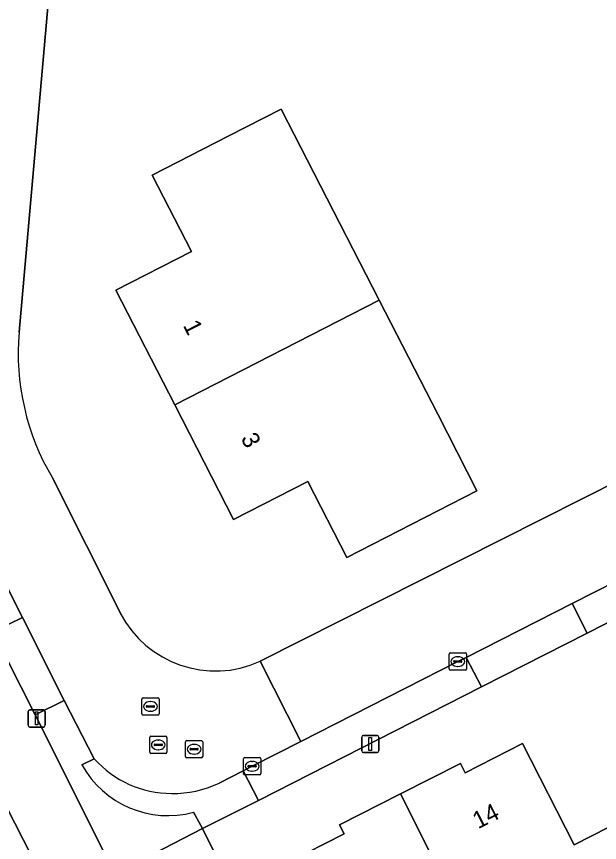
# Model space of a CAD drawing. Extents: x 162722 to 165104, y 384719 to 386284.
# Drawn here: x 163950.78 to 163984.67, y 385101.85 to 385149.88 of the extents above; entities that cross this region are included whole.
import ezdxf

# ---------------------------------------------------------------- set-up
doc = ezdxf.new("R2010")
doc.units = 0
for name, color, linetype in [('IMGEO_Erf', 7, 'Continuous'), ('IMGEO_Kolk', 7, 'Continuous'), ('IMGEO_Lichtmast', 7, 'Continuous'), ('IMGEO_Pand', 7, 'Continuous'), ('IMGEO_Pand_nummerreeks', 7, 'Continuous'), ('IMGEO_Parkeervlak_open', 7, 'Continuous'), ('IMGEO_Rijbaan_lokaal_gesloten', 7, 'Continuous'), ('IMGEO_Rioolput', 7, 'Continuous'), ('IMGEO_Voetpad_open', 7, 'Continuous')]:
    doc.layers.add(name, color=color, linetype=linetype)

msp = doc.modelspace()

# ---------------------------------------------------------------- linework, layer by layer
at = {"layer": 'IMGEO_Erf'}
for points in [[(163954.865, 385176.188), (163950.926, 385131.52)], [(163925.634, 385124.386), (163926.79, 385136.924), (163927.93, 385149.301), (163931.403, 385148.981), (163936.381, 385148.522), (163935.933, 385143.661), (163940.873, 385143.206), (163940.181, 385135.69), (163939.488, 385128.173), (163934.624, 385128.621), (163934.161, 385123.598), (163935.481, 385121.023), (163935.921, 385121.248), (163938.196, 385116.808), (163942.568, 385119.048), (163946.07, 385112.214), (163941.667, 385109.956), (163943.925, 385105.548), (163948.225, 385107.751), (163951.644, 385101.078)], [(163964.943, 385112.381), (164000, 385130.066), (164025.009, 385142.682)], [(163952.865, 385123.051), (163956.817, 385115.183)], [(163956.503, 385100.031), (163951.859, 385109.26), (163949.405, 385114.092), (163945.936, 385121.003)], [(163997.359, 385120.835), (163983.951, 385114.019), (163977.81, 385110.894), (163964.844, 385104.297), (163961.595, 385102.65), (163964.334, 385097.182), (163965.557, 385094.815), (163966.315, 385093.275), (163969.491, 385094.891), (163968.713, 385096.419), (163966.546, 385100.679), (163969.83, 385102.351), (163969.568, 385102.866), (163973.106, 385104.666), (163976.594, 385106.441), (163976.87, 385105.899), (163980.209, 385107.598), (163983.201, 385101.719), (163986.206, 385103.248)]]:
    msp.add_lwpolyline(points, dxfattribs=at)
msp.add_lwpolyline([(163975.271, 385126.75), (163977.551, 385122.3), (163969.982, 385118.421), (163967.715, 385122.845), (163963.394, 385120.631), (163959.98, 385127.292), (163956.564, 385133.957), (163960.956, 385136.208), (163958.676, 385140.656), (163963.126, 385142.937), (163966.174, 385144.499), (163971.87, 385133.386)], close=True, dxfattribs=at)
for centre, radius, start, end in [((163965.158, 385130.322), 14.282, 175.1881, 210.6034), ((163962.351, 385118.049), 6.233, 207.3794, 294.5703)]:
    msp.add_arc(centre, radius, start, end, dxfattribs=at)
at = {"layer": 'IMGEO_Kolk'}
for p, q in [((163975.937, 385111.943), (163975.937, 385112.795)), ((163976.012, 385112.869), (163976.864, 385112.869)), ((163976.425, 385112.649), (163976.45, 385112.649)), ((163976.938, 385112.795), (163976.938, 385111.943)), ((163976.196, 385112.363), (163976.196, 385112.375)), ((163976.634, 385112.326), (163976.236, 385112.326)), ((163976.239, 385112.412), (163976.637, 385112.412)), ((163976.68, 385112.375), (163976.68, 385112.363)), ((163976.864, 385111.869), (163976.012, 385111.869)), ((163976.448, 385112.089), (163976.423, 385112.089)), ((163963.979, 385105.853), (163963.979, 385106.705)), ((163964.054, 385106.779), (163964.906, 385106.779)), ((163964.467, 385106.559), (163964.492, 385106.559)), ((163964.98, 385106.705), (163964.98, 385105.853)), ((163964.238, 385106.273), (163964.238, 385106.285)), ((163964.676, 385106.236), (163964.278, 385106.236)), ((163964.281, 385106.322), (163964.679, 385106.322)), ((163964.49, 385105.999), (163964.465, 385105.999)), ((163964.722, 385106.285), (163964.722, 385106.273)), ((163964.906, 385105.779), (163964.054, 385105.779))]:
    msp.add_line(p, q, dxfattribs=at)
for points in [[(163975.937, 385111.943), (163975.937, 385112.795)], [(163976.012, 385112.869), (163976.864, 385112.869)], [(163976.938, 385112.795), (163976.938, 385111.943)], [(163976.864, 385111.869), (163976.012, 385111.869)], [(163963.979, 385105.853), (163963.979, 385106.705)], [(163964.054, 385106.779), (163964.906, 385106.779)], [(163964.98, 385106.705), (163964.98, 385105.853)], [(163964.906, 385105.779), (163964.054, 385105.779)]]:
    msp.add_lwpolyline(points, dxfattribs=at)
for centre, radius, start, end in [((163976.014, 385112.793), 0.0765, 91.552, 178.448), ((163976.014, 385112.793), 0.0765, 91.552, 178.448), ((163976.862, 385112.793), 0.0765, 1.552, 88.448), ((163976.862, 385112.793), 0.0765, 1.552, 88.448), ((163976.236, 385112.372), 0.0403, 85.8775, 175.7526), ((163976.233, 385112.362), 0.0366, 178.938, 274.7102), ((163976.637, 385112.369), 0.043, 264.8664, 352.4533), ((163976.641, 385112.374), 0.0386, 1.7309, 96.639), ((163976.014, 385111.945), 0.0765, 181.552, 268.448), ((163976.014, 385111.945), 0.0765, 181.552, 268.448), ((163976.862, 385111.945), 0.0765, 271.552, 358.448), ((163976.862, 385111.945), 0.0765, 271.552, 358.448), ((163964.056, 385106.703), 0.0765, 91.552, 178.448), ((163964.056, 385106.703), 0.0765, 91.552, 178.448), ((163964.904, 385106.703), 0.0765, 1.552, 88.448), ((163964.904, 385106.703), 0.0765, 1.552, 88.448), ((163964.278, 385106.282), 0.0403, 85.8775, 175.7526), ((163964.275, 385106.272), 0.0366, 178.938, 274.7102), ((163964.679, 385106.279), 0.043, 264.8664, 352.4533), ((163964.683, 385106.284), 0.0386, 1.7309, 96.639), ((163964.056, 385105.855), 0.0765, 181.552, 268.448), ((163964.056, 385105.855), 0.0765, 181.552, 268.448), ((163964.904, 385105.855), 0.0765, 271.552, 358.448), ((163964.904, 385105.855), 0.0765, 271.552, 358.448)]:
    msp.add_arc(centre, radius, start, end, dxfattribs=at)
for centre, major_axis, ratio, start_param, end_param in [((163976.424, 385112.369), (-0.387, 0.002), 0.722429, 4.712389, 7.853982), ((163976.449, 385112.369), (-0.39, 0.002), 0.717154, 1.570796, 4.712389), ((163964.466, 385106.279), (-0.387, 0.002), 0.722429, 4.712389, 7.853982), ((163964.491, 385106.279), (-0.39, 0.002), 0.717154, 1.570796, 4.712389)]:
    msp.add_ellipse(centre, major_axis=major_axis, ratio=ratio, start_param=start_param, end_param=end_param, dxfattribs=at)
at = {"layer": 'IMGEO_Lichtmast'}
for p, q in [((163951.455, 385108.66), (163951.455, 385109.46)), ((163951.455, 385109.46), (163951.455, 385108.66)), ((163951.555, 385109.56), (163952.345, 385109.56)), ((163952.345, 385109.56), (163951.555, 385109.56)), ((163952.445, 385109.46), (163952.445, 385108.66)), ((163952.445, 385108.66), (163952.445, 385109.46)), ((163952.345, 385108.56), (163951.555, 385108.56)), ((163951.555, 385108.56), (163952.345, 385108.56)), ((163970.85, 385107.171), (163970.85, 385107.971)), ((163970.85, 385107.971), (163970.85, 385107.171)), ((163970.95, 385108.071), (163971.74, 385108.071)), ((163971.74, 385108.071), (163970.95, 385108.071)), ((163971.84, 385107.971), (163971.84, 385107.171)), ((163971.84, 385107.171), (163971.84, 385107.971)), ((163971.74, 385107.071), (163970.95, 385107.071)), ((163970.95, 385107.071), (163971.74, 385107.071))]:
    msp.add_line(p, q, dxfattribs=at)
for points in [[(163951.875, 385109.435), (163952.025, 385109.435), (163952.025, 385108.685), (163951.875, 385108.685), (163951.875, 385109.435)], [(163971.27, 385107.946), (163971.42, 385107.946), (163971.42, 385107.196), (163971.27, 385107.196), (163971.27, 385107.946)]]:
    msp.add_lwpolyline(points, dxfattribs=at)
for centre, start, end in [((163951.555, 385109.46), 90, 180), ((163951.555, 385109.46), 90, 180), ((163952.345, 385109.46), 0, 90), ((163952.345, 385109.46), 360, 90), ((163951.555, 385108.66), 180, 270), ((163951.555, 385108.66), 180, 270), ((163952.345, 385108.66), 270, 0), ((163952.345, 385108.66), 270, 0), ((163970.95, 385107.971), 90, 180), ((163970.95, 385107.971), 90, 180), ((163971.74, 385107.971), 0, 90), ((163971.74, 385107.971), 360, 90), ((163970.95, 385107.171), 180, 270), ((163970.95, 385107.171), 180, 270), ((163971.74, 385107.171), 270, 0), ((163971.74, 385107.171), 270, 0)]:
    msp.add_arc(centre, 0.1, start, end, dxfattribs=at)
at = {"layer": 'IMGEO_Pand'}
for points in [[(163971.87, 385133.386), (163966.174, 385144.499), (163963.126, 385142.937), (163958.676, 385140.656), (163960.956, 385136.208), (163956.564, 385133.957), (163959.98, 385127.292)], [(163959.98, 385127.292), (163963.394, 385120.631), (163967.715, 385122.845), (163969.982, 385118.421), (163977.551, 385122.3), (163975.271, 385126.75), (163971.87, 385133.386)], [(163948.225, 385107.751), (163943.925, 385105.548), (163941.667, 385109.956), (163934.076, 385106.062), (163939.752, 385094.983), (163951.644, 385101.078)], [(163977.672, 385095.566), (163977.771, 385095.617), (163981.269, 385097.397), (163983.178, 385093.646), (163989.429, 385096.827), (163986.206, 385103.248), (163983.201, 385101.719), (163980.209, 385107.598), (163976.87, 385105.899), (163976.594, 385106.441), (163973.106, 385104.666)], [(163969.592, 385086.835), (163975.899, 385090.044), (163974.982, 385091.845), (163978.722, 385093.748), (163977.771, 385095.617), (163977.672, 385095.566), (163973.106, 385104.666), (163969.568, 385102.866), (163969.83, 385102.351), (163966.546, 385100.679), (163968.713, 385096.419), (163969.491, 385094.891), (163966.315, 385093.275)]]:
    msp.add_lwpolyline(points, close=True, dxfattribs=at)
at = {"layer": 'IMGEO_Parkeervlak_open'}
msp.add_lwpolyline([(163961.78, 385091.125), (163964.247, 385092.383), (163964.444, 385092.483), (163962.467, 385096.254), (163964.334, 385097.182), (163961.595, 385102.65), (163956.503, 385100.031), (163960.697, 385091.697), (163961.147, 385090.802)], close=True, dxfattribs=at)
at = {"layer": 'IMGEO_Rijbaan_lokaal_gesloten'}
for points in [[(163950.926, 385131.52), (163954.865, 385176.188)], [(164025.009, 385142.682), (164000, 385130.066), (163964.943, 385112.381), (163967.315, 385107.723), (163976.438, 385112.369), (163976.92, 385112.606), (163983.085, 385115.734), (163989.577, 385119.038), (163996.493, 385122.545), (164000, 385124.341), (164000.916, 385124.81), (164002.466, 385125.576), (164013.005, 385130.942)], [(163956.817, 385115.183), (163952.865, 385123.051)], [(163947.623, 385121.871), (163950.186, 385116.813), (163951.121, 385114.939), (163953.559, 385110.107), (163955.301, 385106.72)], [(163962.555, 385105.297), (163963.962, 385106.012), (163964.48, 385106.279), (163967.315, 385107.723), (163964.943, 385112.381)]]:
    msp.add_lwpolyline(points, dxfattribs=at)
for centre, radius, start, end in [((163965.158, 385130.322), 14.282, 175.1881, 210.6034), ((163962.351, 385118.049), 6.233, 207.3794, 294.5703), ((163959.806, 385110.722), 6.026, 221.6166, 269.9014), ((163959.867, 385111.001), 6.306, 269.3503, 295.2275)]:
    msp.add_arc(centre, radius, start, end, dxfattribs=at)
at = {"layer": 'IMGEO_Rioolput'}
for p, q in [((163958.142, 385110.257), (163958.994, 385110.257)), ((163958.067, 385109.331), (163958.067, 385110.183)), ((163958.326, 385109.751), (163958.326, 385109.763)), ((163958.369, 385109.8), (163958.767, 385109.8)), ((163958.555, 385110.037), (163958.58, 385110.037)), ((163958.81, 385109.763), (163958.81, 385109.751)), ((163959.068, 385110.183), (163959.068, 385109.331)), ((163958.994, 385109.257), (163958.142, 385109.257)), ((163958.764, 385109.714), (163958.366, 385109.714)), ((163958.578, 385109.477), (163958.553, 385109.477)), ((163958.524, 385107.097), (163958.524, 385107.949)), ((163958.599, 385108.023), (163959.451, 385108.023)), ((163959.525, 385107.949), (163959.525, 385107.097)), ((163958.783, 385107.517), (163958.783, 385107.529)), ((163959.221, 385107.48), (163958.823, 385107.48)), ((163958.826, 385107.566), (163959.224, 385107.566)), ((163959.012, 385107.803), (163959.037, 385107.803)), ((163959.267, 385107.529), (163959.267, 385107.517)), ((163960.605, 385106.843), (163960.605, 385107.695)), ((163960.68, 385107.769), (163961.532, 385107.769)), ((163961.093, 385107.549), (163961.118, 385107.549)), ((163961.606, 385107.695), (163961.606, 385106.843)), ((163959.451, 385107.023), (163958.599, 385107.023)), ((163959.035, 385107.243), (163959.01, 385107.243)), ((163960.864, 385107.263), (163960.864, 385107.275)), ((163961.302, 385107.226), (163960.904, 385107.226)), ((163960.907, 385107.312), (163961.305, 385107.312)), ((163961.116, 385106.989), (163961.091, 385106.989)), ((163961.348, 385107.275), (163961.348, 385107.263)), ((163961.532, 385106.769), (163960.68, 385106.769))]:
    msp.add_line(p, q, dxfattribs=at)
for points in [[(163958.142, 385110.257), (163958.994, 385110.257)], [(163958.067, 385109.331), (163958.067, 385110.183)], [(163959.068, 385110.183), (163959.068, 385109.331)], [(163958.994, 385109.257), (163958.142, 385109.257)], [(163958.524, 385107.097), (163958.524, 385107.949)], [(163958.599, 385108.023), (163959.451, 385108.023)], [(163959.525, 385107.949), (163959.525, 385107.097)], [(163960.605, 385106.843), (163960.605, 385107.695)], [(163960.68, 385107.769), (163961.532, 385107.769)], [(163961.606, 385107.695), (163961.606, 385106.843)], [(163959.451, 385107.023), (163958.599, 385107.023)], [(163961.532, 385106.769), (163960.68, 385106.769)]]:
    msp.add_lwpolyline(points, dxfattribs=at)
for centre, radius, start, end in [((163958.144, 385110.181), 0.0765, 91.552, 178.448), ((163958.144, 385110.181), 0.0765, 91.552, 178.448), ((163958.992, 385110.181), 0.0765, 1.552, 88.448), ((163958.992, 385110.181), 0.0765, 1.552, 88.448), ((163958.366, 385109.76), 0.0403, 85.8775, 175.7526), ((163958.363, 385109.75), 0.0366, 178.938, 274.7102), ((163958.767, 385109.757), 0.043, 264.8664, 352.4533), ((163958.771, 385109.762), 0.0386, 1.7309, 96.639), ((163958.144, 385109.333), 0.0765, 181.552, 268.448), ((163958.144, 385109.333), 0.0765, 181.552, 268.448), ((163958.992, 385109.333), 0.0765, 271.552, 358.448), ((163958.992, 385109.333), 0.0765, 271.552, 358.448), ((163958.601, 385107.947), 0.0765, 91.552, 178.448), ((163958.601, 385107.947), 0.0765, 91.552, 178.448), ((163959.449, 385107.947), 0.0765, 1.552, 88.448), ((163959.449, 385107.947), 0.0765, 1.552, 88.448), ((163958.823, 385107.526), 0.0403, 85.8775, 175.7526), ((163958.82, 385107.516), 0.0366, 178.938, 274.7102), ((163959.224, 385107.523), 0.043, 264.8664, 352.4533), ((163959.228, 385107.528), 0.0386, 1.7309, 96.639), ((163960.682, 385107.693), 0.0765, 91.552, 178.448), ((163960.682, 385107.693), 0.0765, 91.552, 178.448), ((163961.53, 385107.693), 0.0765, 1.552, 88.448), ((163961.53, 385107.693), 0.0765, 1.552, 88.448), ((163958.601, 385107.099), 0.0765, 181.552, 268.448), ((163958.601, 385107.099), 0.0765, 181.552, 268.448), ((163959.449, 385107.099), 0.0765, 271.552, 358.448), ((163959.449, 385107.099), 0.0765, 271.552, 358.448), ((163960.904, 385107.272), 0.0403, 85.8775, 175.7526), ((163960.901, 385107.262), 0.0366, 178.938, 274.7102), ((163961.305, 385107.269), 0.043, 264.8664, 352.4533), ((163961.309, 385107.274), 0.0386, 1.7309, 96.639), ((163960.682, 385106.845), 0.0765, 181.552, 268.448), ((163960.682, 385106.845), 0.0765, 181.552, 268.448), ((163961.53, 385106.845), 0.0765, 271.552, 358.448), ((163961.53, 385106.845), 0.0765, 271.552, 358.448)]:
    msp.add_arc(centre, radius, start, end, dxfattribs=at)
for centre, major_axis, ratio, start_param, end_param in [((163958.554, 385109.757), (-0.387, 0.002), 0.722429, 4.712389, 7.853982), ((163958.579, 385109.757), (-0.39, 0.002), 0.717154, 1.570796, 4.712389), ((163959.011, 385107.523), (-0.387, 0.002), 0.722429, 4.712389, 7.853982), ((163959.036, 385107.523), (-0.39, 0.002), 0.717154, 1.570796, 4.712389), ((163961.092, 385107.269), (-0.387, 0.002), 0.722429, 4.712389, 7.853982), ((163961.117, 385107.269), (-0.39, 0.002), 0.717154, 1.570796, 4.712389)]:
    msp.add_ellipse(centre, major_axis=major_axis, ratio=ratio, start_param=start_param, end_param=end_param, dxfattribs=at)
at = {"layer": 'IMGEO_Voetpad_open'}
for points in [[(163996.493, 385122.545), (163989.577, 385119.038), (163983.085, 385115.734), (163983.951, 385114.019), (163997.359, 385120.835)], [(163945.936, 385121.003), (163949.405, 385114.092), (163951.121, 385114.939), (163950.186, 385116.813), (163947.623, 385121.871)], [(163983.085, 385115.734), (163976.92, 385112.606), (163977.81, 385110.894), (163983.951, 385114.019)], [(163949.405, 385114.092), (163951.859, 385109.26), (163953.559, 385110.107), (163951.121, 385114.939)], [(163977.81, 385110.894), (163976.92, 385112.606), (163976.438, 385112.369), (163967.315, 385107.723), (163964.48, 385106.279), (163963.962, 385106.012), (163964.844, 385104.297)]]:
    msp.add_lwpolyline(points, close=True, dxfattribs=at)
for points in [[(163954.586, 385106.357), (163955.301, 385106.72), (163953.559, 385110.107), (163951.859, 385109.26), (163956.503, 385100.031), (163961.595, 385102.65), (163961.076, 385103.602)], [(163955.301, 385106.72), (163954.586, 385106.357)], [(163961.076, 385103.602), (163961.595, 385102.65), (163964.844, 385104.297), (163963.962, 385106.012)], [(163963.962, 385106.012), (163962.555, 385105.297)]]:
    msp.add_lwpolyline(points, dxfattribs=at)
for centre, radius, start, end in [((163959.806, 385110.722), 6.026, 221.6166, 269.9014), ((163959.594, 385109.133), 5.726, 208.9982, 284.9995), ((163959.594, 385109.133), 5.726, 208.9982, 284.9995), ((163959.867, 385111.001), 6.306, 269.3503, 295.2275)]:
    msp.add_arc(centre, radius, start, end, dxfattribs=at)

# ---------------------------------------------------------------- texts
at = {"layer": 'IMGEO_Pand_nummerreeks'}
for s, rotation, p in [('1', 297.1366, (163960.44, 385131.918)), ('3', 297.1366, (163963.803, 385125.356)), ('14', 26.8578, (163977.618, 385102.609))]:
    msp.add_text(s, height=1, rotation=rotation, dxfattribs=at).set_placement(p)

doc.saveas('drawing.dxf')
